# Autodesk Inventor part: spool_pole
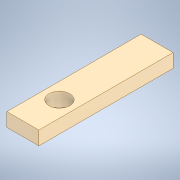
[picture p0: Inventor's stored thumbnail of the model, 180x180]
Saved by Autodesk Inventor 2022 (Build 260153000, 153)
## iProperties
Created: 2021-06
Part Number: spool_pole
Material: Generic
Document SubType Name: Modeling
Designer: Chimms
Density: 1 g/cm^3
Appearance: Smooth - Off-White
Author: Chimms
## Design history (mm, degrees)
sketch "Sketch1"
  geometry: L1 (0, 0)-(35, 0); L2 (35, 0)-(35, 35); L3 (35, 35)-(0, 35); L4 (0, 35)-(0, 0)
  constraints: 8 end point, 2 parallel, 1 horizontal, 1 perpendicular
  dimensions: "d0" = 35 distance of L3.end L2.end; "d1" = 35 distance of L2.end L1.end
extrude "Extrusion1" new body sketch "Sketch1" distance "d2" = 122; taper "d3" = 0 deg
sketch "Sketch2"
  geometry: L1 (35, 122)-(0, 122) reference; L2 (17.5, 122)-(17.5, 82); C1 r 11.389 at (17.5, 82); 1 further point
  constraints: 2 end point, 1 centre point, 1 coincident, 1 midpoint, 1 vertical
  dimensions: "d4" = 40 distance of L2.start L2.end; "d5" = 22.778 diameter of C1
extrude "Extrusion2" cut sketch "Sketch2" extent not by distance; stored distance "d6" = 0; taper "d7" = 0 deg
sketch "Sketch3"
  geometry: L1 (-35, 35)-(0, 35); L2 (0, 35)-(0, 20); L3 (0, 20)-(-35, 20); L4 (-35, 20)-(-35, 35); 1 further point
  constraints: 8 end point, 2 parallel, 1 horizontal, 1 perpendicular
  dimensions: "d8" = 35 distance of L2.end L3.end; "d9" = 15 distance of L1.end L2.end
extrude "Extrusion3" cut sketch "Sketch3" extent not by distance; stored distance "d10" = 0; taper "d11" = 0 deg
sketch "Sketch4"
  geometry: L1 (-35, 0)-(-35, 20) reference; L2 (-35, 20)-(0, 20); L3 (0, 20)-(0, 15); L4 (0, 15)-(-35, 15); L5 (-35, 15)-(-35, 20); 2 further points
  constraints: 8 end point, 2 parallel, 1 horizontal, 1 perpendicular
  dimensions: "d12" = 35 distance of L3.end L4.end; "d13" = 5 distance of L2.end L3.end
extrude "Extrusion4" cut sketch "Sketch4" extent not by distance; stored distance "d14" = 0; taper "d15" = 0 deg
sketch "Sketch5"
  geometry: L1 (0, 0)-(35, 0); L2 (35, 0)-(35, -25); L3 (35, -25)-(0, -25); L4 (0, -25)-(0, 0)
  constraints: 8 end point, 2 parallel, 1 horizontal, 1 perpendicular
  dimensions: "d16" = 35 distance of L2.end L3.end; "d17" = 25 distance of L1.end L2.end
extrude "Extrusion5" join sketch "Sketch5" distance "d18" = 15; taper "d19" = 0 deg
body "Solid1"
